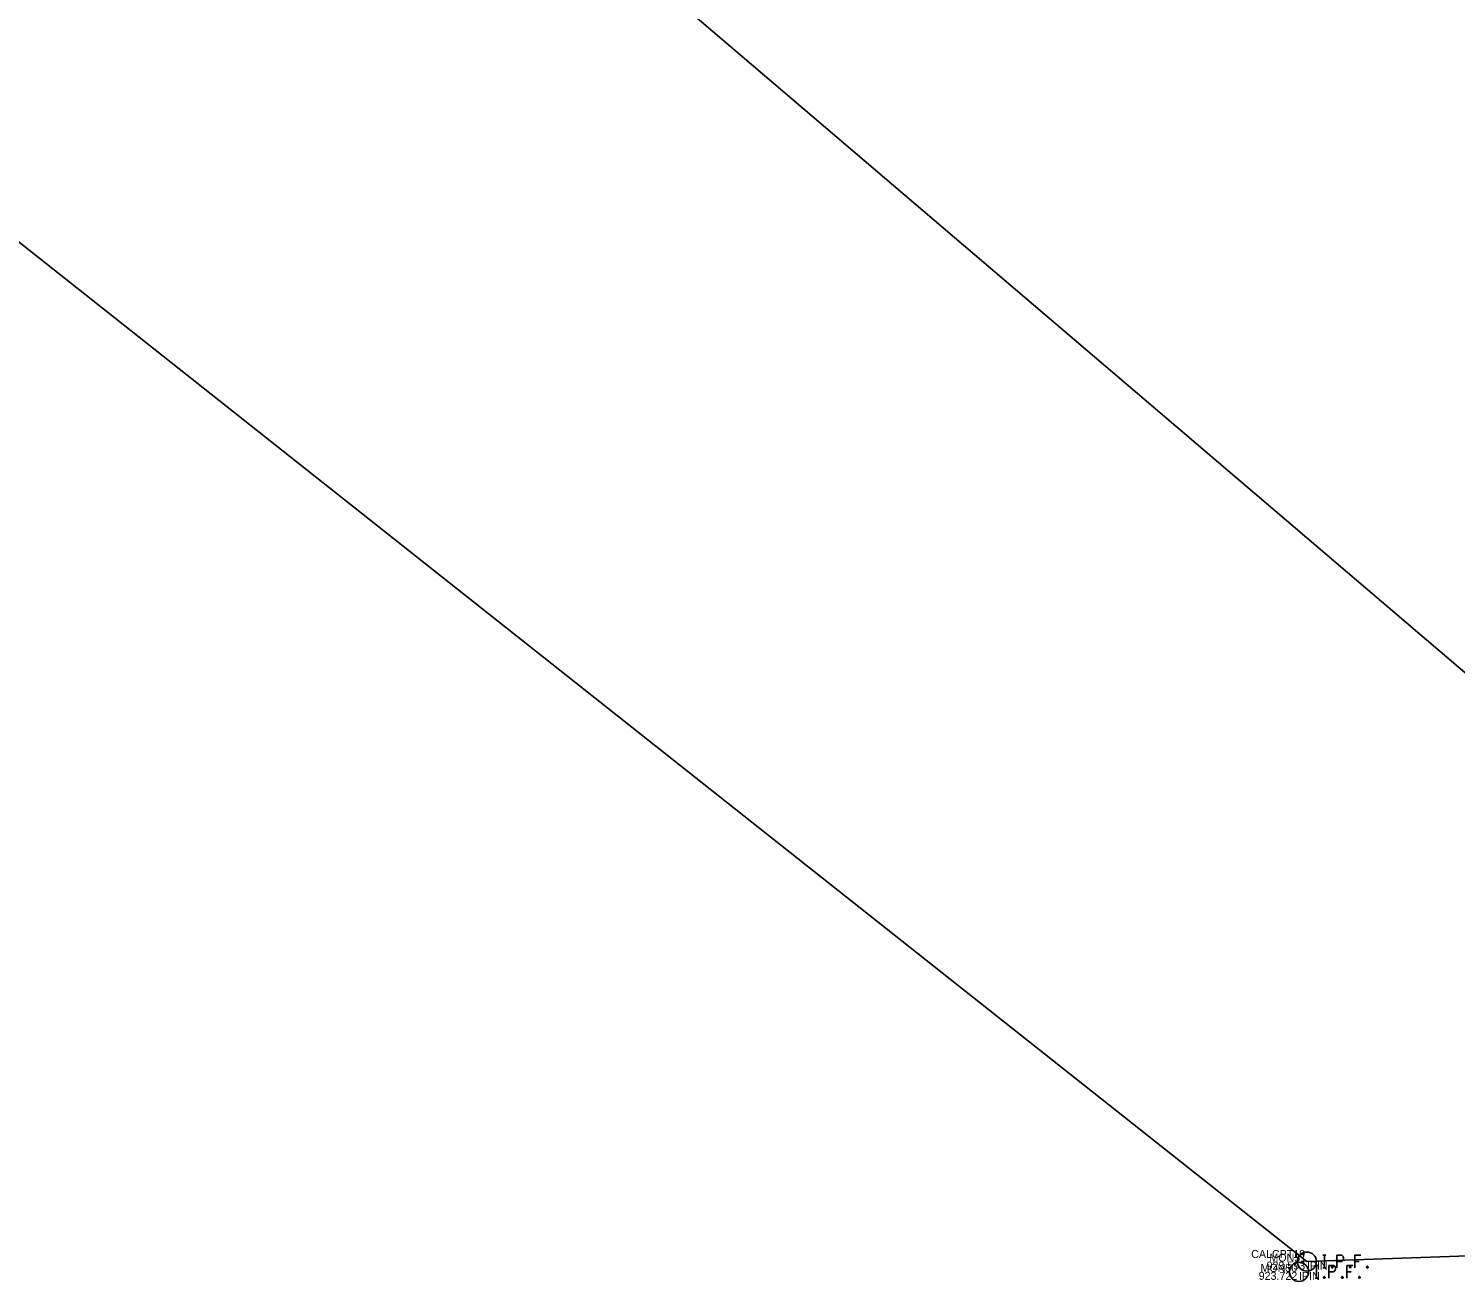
# Model space of a CAD drawing. Extents: x 1981066 to 1984208, y 708139 to 709503.
# Drawn here: x 1983850.2 to 1984029.1, y 708392.1 to 708549.2 of the extents above; entities that cross this region are included whole.
import ezdxf

# ---------------------------------------------------------------- set-up
doc = ezdxf.new("R2010")
doc.units = 0
for name, color, linetype in [('DR_X_Ditch', 7, 'Continuous'), ('DR_X_Elev_Flow', 7, 'Continuous'), ('LT_X_Poles', 7, 'Continuous'), ('SV_X_Shot_Marker', 7, 'Continuous'), ('SV_X_Toe_of_Slope', 7, 'Continuous'), ('UT_X_Misc_Cells', 7, 'Continuous')]:
    doc.layers.add(name, color=color, linetype=linetype)

msp = doc.modelspace()

# ---------------------------------------------------------------- linework, layer by layer
at = {"layer": 'DR_X_Ditch'}
msp.add_line((1983707.34, 708743.91), (1984112.67, 708398.18), dxfattribs=at)
at = {"layer": 'SV_X_Shot_Marker'}
for points in [[(1984012.52, 708395.36), (1984012.87, 708395.36)], [(1984012.69, 708393.76), (1984012.69, 708395.36)], [(1984014.26, 708393.76), (1984014.26, 708395.36), (1984014.79, 708395.36), (1984014.84, 708395.35), (1984014.92, 708395.32), (1984014.95, 708395.3), (1984014.98, 708395.27), (1984015.03, 708395.21), (1984015.06, 708395.15), (1984015.08, 708395.04), (1984015.08, 708394.89), (1984015.07, 708394.84), (1984015.05, 708394.77), (1984015.01, 708394.68), (1984014.96, 708394.64), (1984014.93, 708394.62), (1984014.87, 708394.59), (1984014.79, 708394.58), (1984014.26, 708394.58)], [(1984017.27, 708395.36), (1984016.51, 708395.36), (1984016.51, 708393.76)], [(1984011.53, 708394.06), (1984011.88, 708394.06)], [(1984011.7, 708392.46), (1984011.7, 708394.06)], [(1984012.52, 708393.76), (1984012.87, 708393.76)], [(1984013.27, 708392.46), (1984013.27, 708394.06), (1984013.8, 708394.06), (1984013.85, 708394.05), (1984013.93, 708394.03), (1984013.96, 708394), (1984014, 708393.98), (1984014.04, 708393.91), (1984014.07, 708393.85), (1984014.1, 708393.75), (1984014.1, 708393.6), (1984014.09, 708393.55), (1984014.06, 708393.47), (1984014.02, 708393.38), (1984013.98, 708393.35), (1984013.94, 708393.32), (1984013.89, 708393.3), (1984013.8, 708393.28), (1984013.27, 708393.28)], [(1984013.65, 708393.97), (1984013.71, 708393.97), (1984013.74, 708393.95), (1984013.77, 708393.9), (1984013.77, 708393.84), (1984013.74, 708393.79), (1984013.71, 708393.76), (1984013.65, 708393.76), (1984013.62, 708393.79), (1984013.58, 708393.84), (1984013.58, 708393.9), (1984013.62, 708393.95), (1984013.65, 708393.97)], [(1984016.28, 708394.06), (1984015.52, 708394.06), (1984015.52, 708392.46)], [(1984015.52, 708393.28), (1984016.06, 708393.28)], [(1984015.9, 708393.97), (1984015.95, 708393.97), (1984015.99, 708393.95), (1984016.02, 708393.9), (1984016.02, 708393.84), (1984015.99, 708393.79), (1984015.95, 708393.76), (1984015.9, 708393.76), (1984015.87, 708393.79), (1984015.83, 708393.84), (1984015.83, 708393.9), (1984015.87, 708393.95), (1984015.9, 708393.97)], [(1984016.51, 708394.58), (1984017.05, 708394.58)], [(1984018.05, 708393.97), (1984018.1, 708393.97), (1984018.14, 708393.95), (1984018.17, 708393.9), (1984018.17, 708393.84), (1984018.14, 708393.79), (1984018.1, 708393.76), (1984018.05, 708393.76), (1984018.02, 708393.79), (1984017.98, 708393.84), (1984017.98, 708393.9), (1984018.02, 708393.95), (1984018.05, 708393.97)], [(1984011.53, 708392.46), (1984011.88, 708392.46)], [(1984012.66, 708392.68), (1984012.72, 708392.68), (1984012.75, 708392.65), (1984012.78, 708392.6), (1984012.78, 708392.54), (1984012.75, 708392.49), (1984012.72, 708392.46), (1984012.66, 708392.46), (1984012.63, 708392.49), (1984012.6, 708392.54), (1984012.6, 708392.6), (1984012.63, 708392.65), (1984012.66, 708392.68)], [(1984014.91, 708392.68), (1984014.97, 708392.68), (1984015, 708392.65), (1984015.03, 708392.6), (1984015.03, 708392.54), (1984015, 708392.49), (1984014.97, 708392.46), (1984014.91, 708392.46), (1984014.88, 708392.49), (1984014.85, 708392.54), (1984014.85, 708392.6), (1984014.88, 708392.65), (1984014.91, 708392.68)], [(1984017.06, 708392.68), (1984017.12, 708392.68), (1984017.15, 708392.65), (1984017.18, 708392.6), (1984017.18, 708392.54), (1984017.15, 708392.49), (1984017.12, 708392.46), (1984017.06, 708392.46), (1984017.03, 708392.49), (1984017, 708392.54), (1984017, 708392.6), (1984017.03, 708392.65), (1984017.06, 708392.68)]]:
    msp.add_lwpolyline(points, dxfattribs=at)
for centre in [(1984010.5, 708394.56), (1984009.51, 708393.27)]:
    msp.add_circle(centre, 1.2, dxfattribs=at)
at = {"layer": 'SV_X_Toe_of_Slope'}
for p, q in [((1983659.59, 708672.43), (1984010.5, 708394.56)), ((1984010.5, 708394.56), (1984112.67, 708398.18))]:
    msp.add_line(p, q, dxfattribs=at)

# ---------------------------------------------------------------- texts
at = {"layer": 'DR_X_Elev_Flow'}
for s, p in [('923.722', (1984004.46, 708392.27)), ('923.593', (1984005.45, 708393.56))]:
    msp.add_text(s, height=1, dxfattribs=at).set_placement(p)
at = {"layer": 'LT_X_Poles'}
for p in [(1984009.51, 708392.27), (1984010.5, 708393.56)]:
    msp.add_text('IPIN', height=1, dxfattribs=at).set_placement(p)
at = {"layer": 'UT_X_Misc_Cells'}
for s, p in [('CALCPT19', (1984003.52, 708395.01)), ('MON51', (1984005.8, 708394.56)), ('MON50', (1984004.69, 708393.27))]:
    msp.add_text(s, height=1, dxfattribs=at).set_placement(p)

doc.saveas('drawing.dxf')
